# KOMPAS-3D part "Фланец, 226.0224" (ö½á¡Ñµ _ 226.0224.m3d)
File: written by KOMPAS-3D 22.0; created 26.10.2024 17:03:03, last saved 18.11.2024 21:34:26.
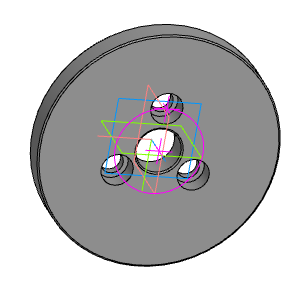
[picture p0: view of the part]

Document properties: Автор: aleksander.larionov.10@gmail.com; Полное имя файла: C:\Мои папки\Работа\Крышки, фланцы\226.0224\Фланец _ 226.0224.m3d

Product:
- Part/product: Фланец  | designation 226.0224
    Материал: Сталь 45 ГОСТ 1050-2013 (density 7810 kg/m3)
    Масса: 2.283354

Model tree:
1. Эскиз:1
2. Элемент выдавливания:1
     Расстояние 1 = 18
3. Эскиз:2  (with: Элемент выдавливания:1)
4. Отверстие:1  (with: Элемент выдавливания:1)
     Глубина выреза = 18; Диаметр отверстия = 14; Угол конуса дна = 118; Расстояние 1 = 27.5; Диаметр цековки = 20; Глубина цековки = 12
5. Массив по концентрической сетке:1  (with: Отверстие:1, Эскиз:2)  (3 pattern instances)
     Шаг 2 = 360
6. Отверстие:2  (with: Элемент выдавливания:1)
     Глубина выреза = 18; Диаметр отверстия = 28; Угол конуса дна = 118
7. Фаска:1  (with: Элемент выдавливания:1, Отверстие:2)  (labels: Сталь 45 ГОСТ 1050-2013)
     Угол = 45; Длина 1 = 1; Длина 2 = 1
